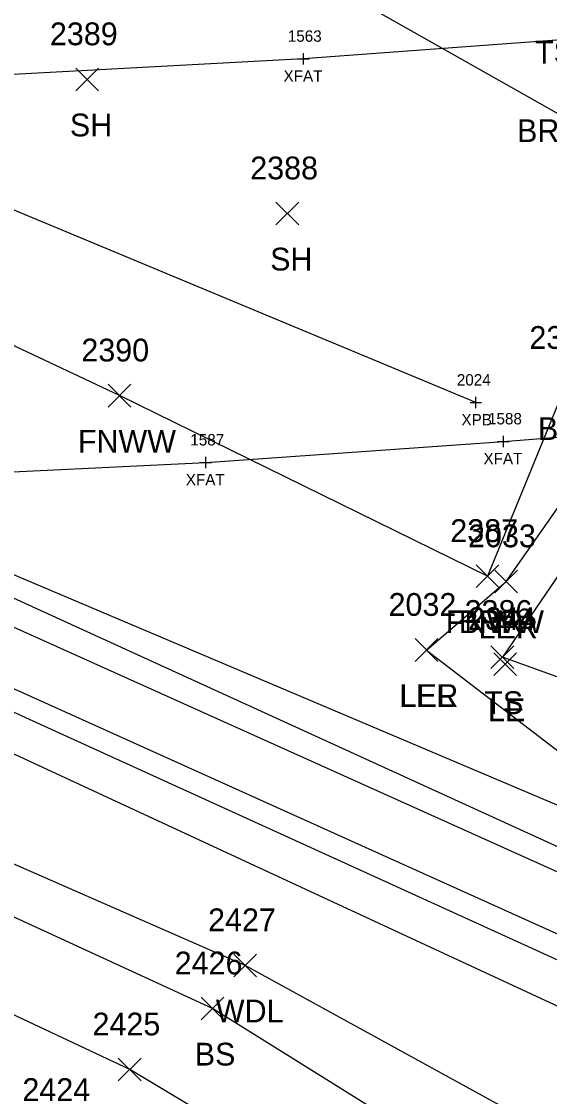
# Model space of a CAD drawing. Extents: x 1599569 to 1610055, y 642560 to 647860.
# Drawn here: x 1601397.5 to 1601443.8, y 647184.7 to 647279.1 of the extents above; entities that cross this region are included whole.
import ezdxf

# ---------------------------------------------------------------- set-up
doc = ezdxf.new("R2010")
doc.units = 0
for name, color, linetype in [('B_A', 7, 'Continuous'), ('B_I', 7, 'Continuous'), ('B_TIC', 7, 'Continuous'), ('BF', 7, 'Continuous'), ('BSUBM', 7, 'Continuous'), ('L_A', 7, 'Continuous'), ('L_I', 7, 'Continuous'), ('L_TIC', 7, 'Continuous'), ('LABL', 7, 'Continuous'), ('LARO', 7, 'Continuous'), ('LAWA', 7, 'Continuous'), ('LELB', 7, 'Continuous'), ('LFNC', 7, 'Continuous'), ('RR', 7, 'Continuous'), ('S_C', 7, 'Continuous')]:
    doc.layers.add(name, color=color, linetype=linetype)

msp = doc.modelspace()

# ---------------------------------------------------------------- linework, layer by layer
at = {"layer": 'B_TIC'}
for p, q in [((1601422.228, 647275.787), (1601422.304, 647275.787)), ((1601437.363, 647245.616), (1601437.439, 647245.616)), ((1601439.777, 647242.204), (1601439.852, 647242.204)), ((1601413.651, 647240.354), (1601413.727, 647240.354))]:
    msp.add_line(p, q, dxfattribs=at)
for points in [[(1601422.225, 647275.287), (1601422.225, 647276.287)], [(1601421.725, 647275.787), (1601422.725, 647275.787)], [(1601437.36, 647245.116), (1601437.36, 647246.116)], [(1601436.86, 647245.616), (1601437.86, 647245.616)], [(1601439.273, 647242.204), (1601440.273, 647242.204)], [(1601439.773, 647241.704), (1601439.773, 647242.704)], [(1601413.148, 647240.354), (1601414.148, 647240.354)], [(1601413.648, 647239.854), (1601413.648, 647240.854)]]:
    msp.add_lwpolyline(points, dxfattribs=at)
at = {"layer": 'BF'}
for points in [[(1601746.01, 647335.352), (1601717.786, 647327.136), (1601692.796, 647320.347), (1601677.173, 647316.267), (1601645.453, 647308.519), (1601618.435, 647302.789), (1601602.804, 647299.49), (1601568.354, 647293.073), (1601543.361, 647288.973), (1601510.507, 647284.259), (1601475.946, 647280.386), (1601455.15, 647278.217), (1601422.225, 647275.787), (1601394.01, 647274.259), (1601380.765, 647273.696), (1601345.12, 647272.82), (1601321.945, 647272.729), (1601290.34, 647273.167)], [(1601288.619, 647238.611), (1601320.658, 647238.008), (1601349.514, 647238.081), (1601373.692, 647238.587), (1601386.361, 647239.047), (1601413.648, 647240.354), (1601439.773, 647242.204), (1601462.417, 647244.022), (1601489.32, 647246.831), (1601509.35, 647249.141), (1601532.763, 647252.337), (1601556.355, 647255.853), (1601578.472, 647259.578), (1601592.93, 647262.14), (1601615.37, 647266.575), (1601636.14, 647270.872), (1601649.722, 647274.107), (1601669.888, 647278.795)]]:
    msp.add_lwpolyline(points, dxfattribs=at)
at = {"layer": 'BSUBM'}
msp.add_lwpolyline([(1601437.36, 647245.616), (1601386.136, 647266.967)], dxfattribs=at)
at = {"layer": 'L_TIC'}
for points in [[(1601402.244, 647272.98), (1601404.244, 647274.98)], [(1601404.244, 647272.98), (1601402.244, 647274.98)], [(1601419.818, 647261.21), (1601421.818, 647263.21)], [(1601421.818, 647261.21), (1601419.818, 647263.21)], [(1601405.085, 647245.227), (1601407.085, 647247.227)], [(1601407.085, 647245.227), (1601405.085, 647247.227)], [(1601437.376, 647229.383), (1601439.376, 647231.383)], [(1601439.376, 647229.383), (1601437.376, 647231.383)], [(1601437.376, 647229.383), (1601439.376, 647231.383)], [(1601439.376, 647229.383), (1601437.376, 647231.383)], [(1601439.016, 647228.92), (1601441.016, 647230.92)], [(1601441.016, 647228.92), (1601439.016, 647230.92)], [(1601432.036, 647222.901), (1601434.036, 647224.901)], [(1601434.036, 647222.901), (1601432.036, 647224.901)], [(1601432.036, 647222.901), (1601434.036, 647224.901)], [(1601434.036, 647222.901), (1601432.036, 647224.901)], [(1601438.686, 647222.281), (1601440.686, 647224.281)], [(1601440.686, 647222.281), (1601438.686, 647224.281)], [(1601438.686, 647222.281), (1601440.686, 647224.281)], [(1601440.686, 647222.281), (1601438.686, 647224.281)], [(1601438.937, 647221.657), (1601440.937, 647223.657)], [(1601440.937, 647221.657), (1601438.937, 647223.657)], [(1601416.12, 647195.223), (1601418.12, 647197.223)], [(1601418.12, 647195.223), (1601416.12, 647197.223)], [(1601413.247, 647191.434), (1601415.247, 647193.434)], [(1601415.247, 647191.434), (1601413.247, 647193.434)], [(1601405.978, 647186.079), (1601407.978, 647188.079)], [(1601407.978, 647186.079), (1601405.978, 647188.079)]]:
    msp.add_lwpolyline(points, dxfattribs=at)
at = {"layer": 'LABL'}
msp.add_lwpolyline([(1601168.989, 647399.27), (1601207.411, 647380.726), (1601257.172, 647358.28), (1601294.194, 647341.701), (1601346.915, 647319.14), (1601374.728, 647304.923), (1601415.903, 647287.209), (1601447.461, 647269.358), (1601451.819, 647260.74), (1601445.32, 647247.332), (1601438.376, 647230.383)], dxfattribs=at)
at = {"layer": 'LARO'}
for points in [[(1601433.036, 647223.901), (1601440.016, 647229.92), (1601448.749, 647242.347), (1601453.33, 647251.542), (1601453.223, 647256.75), (1601455.266, 647258.557), (1601467.283, 647258.568), (1601483.334, 647251.712), (1601513.856, 647240.963), (1601528.533, 647232.926), (1601550.376, 647217.433), (1601552.672, 647208.718), (1601544.619, 647197.575), (1601537.197, 647194.37), (1601523.555, 647194.623), (1601513.269, 647187.664), (1601504.747, 647190.778), (1601495.201, 647190.894), (1601473.71, 647199.593), (1601450.545, 647210.471)], [(1601433.036, 647223.901), (1601450.545, 647210.471)]]:
    msp.add_lwpolyline(points, dxfattribs=at)
at = {"layer": 'LAWA'}
msp.add_lwpolyline([(1601543.96, 647141.4), (1601525.416, 647149.531), (1601489.768, 647162.62), (1601452.935, 647176.559), (1601417.12, 647196.223), (1601382.915, 647211.208), (1601340.765, 647217.08), (1601306.6, 647220.69), (1601276.835, 647227.54)], dxfattribs=at)
at = {"layer": 'LELB'}
for points in [[(1601782.458, 647059.398), (1601738.775, 647079.329), (1601690.401, 647099.929), (1601647.697, 647120.255), (1601610.063, 647137.739), (1601571.922, 647154.07), (1601536.967, 647170.254), (1601497.74, 647186.591), (1601465.753, 647201.272), (1601394.711, 647231.375), (1601362.213, 647245.733), (1601329.864, 647260.178), (1601292.609, 647278.061)], [(1601779.91, 647055.746), (1601736.459, 647075.117), (1601688.287, 647096.705), (1601645.48, 647116.211), (1601608.085, 647132.733), (1601569.651, 647149.891), (1601535.687, 647165.811), (1601496.651, 647183.568), (1601464.02, 647197.75), (1601393.371, 647229.995), (1601361.178, 647244.457), (1601329.078, 647258.95), (1601292.391, 647275.613)], [(1601775.59, 647047.167), (1601732.384, 647067.081), (1601683.695, 647088.906), (1601643.362, 647107.34), (1601603.442, 647124.91), (1601567.985, 647141.64), (1601531.266, 647157.661), (1601493.804, 647174.326), (1601459.44, 647189.896), (1601386.613, 647223.07), (1601358.083, 647235.634), (1601326.17, 647250.648), (1601291.06, 647266.104)], [(1601773.312, 647043.549), (1601729.793, 647062.38), (1601680.122, 647084.111), (1601641.708, 647102.621), (1601602.287, 647120.477), (1601566.233, 647136.755), (1601528.309, 647153.553), (1601493.198, 647170.666), (1601457.645, 647186.549), (1601384.329, 647220.549), (1601356.625, 647233.897), (1601324.867, 647247.724), (1601290.331, 647262.4)], [(1601538.363, 647216.881), (1601522.225, 647228.25), (1601511.295, 647235.841), (1601500.192, 647238.16), (1601496.116, 647237.241), (1601487.069, 647242.996), (1601472.229, 647242.518), (1601465.521, 647251.998), (1601456.518, 647250.25), (1601448.933, 647236.811), (1601439.686, 647223.281)], [(1601480.23, 647219.259), (1601482.527, 647215.519), (1601488.047, 647208.746), (1601486.242, 647203.331), (1601483.996, 647200.282), (1601473.239, 647204.954), (1601463.268, 647211.716), (1601460.469, 647215.795), (1601439.686, 647223.281)], [(1601441.004, 647175.736), (1601414.247, 647192.434), (1601380.273, 647208.065), (1601340.765, 647217.08)], [(1601441.004, 647175.736), (1601432.665, 647171.658), (1601406.978, 647187.079), (1601375.362, 647201.938), (1601340.765, 647217.08)]]:
    msp.add_lwpolyline(points, dxfattribs=at)
at = {"layer": 'LFNC'}
msp.add_lwpolyline([(1601438.376, 647230.383), (1601406.085, 647246.227), (1601390.356, 647253.645), (1601325.066, 647284.525), (1601295.928, 647298.241), (1601277.64, 647306.941), (1601251.54, 647319.321), (1601236.243, 647326.062), (1601200.377, 647343.027), (1601163.893, 647358.89), (1601138.181, 647369.806), (1601105.249, 647383.874), (1601061.326, 647402.551), (1601021.95, 647420.149), (1600970.855, 647443.099), (1600923.386, 647465.039), (1600876.08, 647486.37)], dxfattribs=at)
at = {"layer": 'RR'}
for points in [[(1601779.116, 647053.167), (1601735.091, 647073.164), (1601687.306, 647094.74), (1601644.713, 647114.003), (1601606.946, 647130.881), (1601569.092, 647148.125), (1601534.474, 647163.752), (1601495.861, 647181.284), (1601463.019, 647196.093), (1601391.8, 647228.118), (1601360.223, 647242.534), (1601328.258, 647256.929), (1601292.483, 647273.136)], [(1601776.777, 647048.803), (1601733.224, 647068.551), (1601684.484, 647090.666), (1601642.814, 647109.308), (1601604.47, 647126.663), (1601567.909, 647143.165), (1601532.131, 647159.271), (1601494.468, 647176.347), (1601460.566, 647191.753), (1601388.166, 647224.376), (1601357.498, 647238.3), (1601326.498, 647252.287), (1601291.281, 647268.217)]]:
    msp.add_lwpolyline(points, dxfattribs=at)

# ---------------------------------------------------------------- texts
at = {"layer": 'B_A'}
for s, p in [('XFAT', (1601420.481, 647273.787)), ('XPB', (1601436.096, 647243.616)), ('XFAT', (1601438.029, 647240.204)), ('XFAT', (1601411.904, 647238.354))]:
    msp.add_text(s, height=1, dxfattribs=at).set_placement(p)
at = {"layer": 'B_I'}
for s, p in [('1563', (1601420.855, 647277.287)), ('2024', (1601435.69, 647247.116)), ('1588', (1601438.427, 647243.704)), ('1587', (1601412.301, 647241.854))]:
    msp.add_text(s, height=1, dxfattribs=at).set_placement(p)
at = {"layer": 'L_A'}
for s, p in [('TS', (1601442.556, 647275.373)), ('SH', (1601401.732, 647268.98)), ('SH', (1601419.307, 647257.21)), ('BRR', (1601442.808, 647242.332)), ('FNWW', (1601402.431, 647241.227)), ('FNWW', (1601434.723, 647225.383)), ('BRR', (1601435.865, 647225.383)), ('LER', (1601437.598, 647224.92)), ('LER', (1601430.618, 647218.901)), ('LEL', (1601430.674, 647218.901)), ('TS', (1601438.095, 647218.281)), ('TS', (1601438.095, 647218.281)), ('LE', (1601438.425, 647217.657)), ('WDL', (1601414.537, 647191.223)), ('BS', (1601412.688, 647187.434))]:
    msp.add_text(s, height=2, dxfattribs=at).set_placement(p)
at = {"layer": 'L_I'}
for s, p in [('2389', (1601399.977, 647276.98)), ('2388', (1601417.559, 647265.21)), ('2384', (1601442.06, 647250.332)), ('2390', (1601402.738, 647249.227)), ('2387', (1601435.117, 647233.383)), ('2387', (1601435.117, 647233.383)), ('2033', (1601436.677, 647232.92)), ('2032', (1601429.697, 647226.901)), ('2032', (1601429.697, 647226.901)), ('2386', (1601436.371, 647226.281)), ('2386', (1601436.371, 647226.281)), ('2344', (1601436.677, 647225.657)), ('2427', (1601413.86, 647199.223)), ('2426', (1601410.932, 647195.434)), ('2425', (1601403.718, 647190.079)), ('2424', (1601397.567, 647184.322))]:
    msp.add_text(s, height=2, dxfattribs=at).set_placement(p)
at = {"layer": 'S_C'}
msp.add_text('BRIDGE 44-S I89', height=2, dxfattribs=at).set_placement((1601440.973, 647268.485))

doc.saveas('drawing.dxf')
